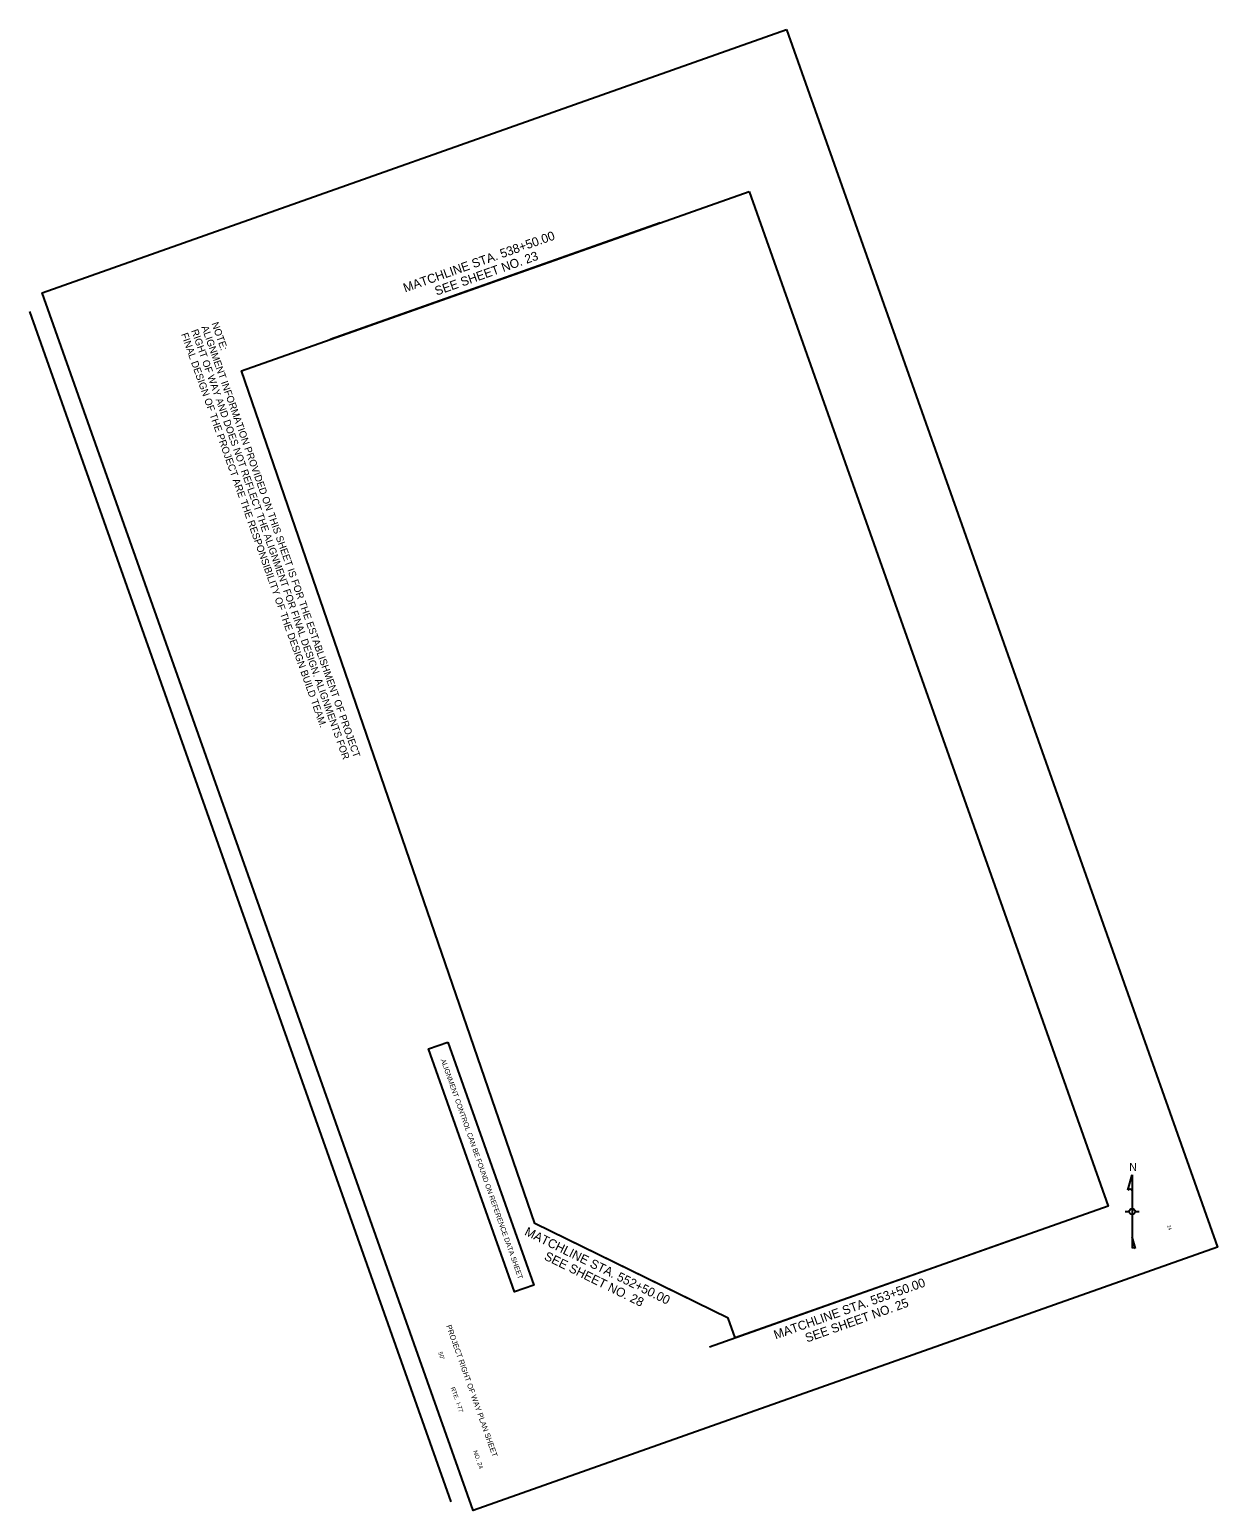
# Model space of a CAD drawing. Extents: x 2004548 to 2006202, y 1137485 to 1139549.
import ezdxf

# ---------------------------------------------------------------- set-up
doc = ezdxf.new("R2010")
doc.units = 0
for name, color, linetype in [('North Arrow', 7, 'Continuous'), ('RD_SHT_IplotShp', 7, 'Continuous'), ('RD_SHT_MatchLine', 7, 'Continuous'), ('RD_SHT_Misc1', 7, 'Continuous'), ('RD_SHT_ShtClip', 7, 'Continuous'), ('RD_SHT_TX', 7, 'Continuous')]:
    doc.layers.add(name, color=color, linetype=linetype)

msp = doc.modelspace()

# ---------------------------------------------------------------- linework, layer by layer
at = {"layer": 'North Arrow'}
for p, q in [((2006077.7, 1137931.5), (2006083.6, 1137952.5)), ((2006083.6, 1137952.5), (2006083.6, 1137930.4)), ((2006083.6, 1137952.5), (2006083.6, 1137850.3)), ((2006073.9, 1137901.4), (2006079.6, 1137901.4)), ((2006087.6, 1137901.4), (2006093.3, 1137901.4)), ((2006083.6, 1137866.1), (2006083.6, 1137850.3)), ((2006088.1, 1137850.1), (2006083.6, 1137866.1))]:
    msp.add_line(p, q, dxfattribs=at)
msp.add_circle((2006083.6, 1137901.4), 4.02, dxfattribs=at)
for centre, radius, start, end in [((2006080.3, 1137929), 3.59, 22.3707, 136.1387), ((2006085.7, 1137847.8), 3.3, 43.3397, 130.5607)]:
    msp.add_arc(centre, radius, start, end, dxfattribs=at)
at = {"layer": 'RD_SHT_IplotShp'}
msp.add_lwpolyline([(2005602, 1139548.8), (2006202.3, 1137851.9), (2005165.3, 1137485), (2004565, 1139181.9)], close=True, dxfattribs=at)
at = {"layer": 'RD_SHT_MatchLine'}
for p, q in [((2005426.1, 1139279.5), (2004966.5, 1139116.9)), ((2005470.7, 1137777.3), (2005251.5, 1137884.9)), ((2005926.3, 1137865.4), (2005494.7, 1137712.7))]:
    msp.add_line(p, q, dxfattribs=at)
at = {"layer": 'RD_SHT_ShtClip'}
msp.add_lwpolyline([(2005549.8, 1139323.3), (2006050.1, 1137909.2), (2005530.3, 1137725.3), (2005520.6, 1137752.8), (2005251.5, 1137884.9), (2004842.7, 1139073.1)], close=True, dxfattribs=at)
at = {"layer": 'RD_SHT_TX'}
msp.add_line((2004547.6, 1139156.1), (2005134.6, 1137496.8), dxfattribs=at)
msp.add_line((2004547.6, 1139156.1), (2005134.6, 1137496.8), dxfattribs=at)
msp.add_lwpolyline([(2005130.3, 1138137.6), (2005250, 1137799), (2005223.3, 1137789.5), (2005103.5, 1138128.1)], close=True, dxfattribs=at)

# ---------------------------------------------------------------- texts
at = {"layer": 'North Arrow'}
msp.add_text('N', height=11.1, dxfattribs=at).set_placement((2006079.5, 1137958))
at = {"layer": 'RD_SHT_MatchLine'}
for s, rotation, p in [('MATCHLINE STA. 538+50.00', 19.482, (2005070.7, 1139182.4)), ('SEE SHEET NO. 23', 19.482, (2005114.6, 1139178)), ('MATCHLINE STA. 552+50.00', 333.8563, (2005236.1, 1137869.4)), ('SEE SHEET NO. 28', 333.8563, (2005263.4, 1137835.1)), ('MATCHLINE STA. 553+50.00', 19.482, (2005586.9, 1137723.3)), ('SEE SHEET NO. 25', 19.482, (2005630.6, 1137718.9))]:
    msp.add_text(s, height=12.5, rotation=rotation, dxfattribs=at).set_placement(p)
at = {"layer": 'RD_SHT_Misc1'}
for s, p in [('NOTE:', (2004800.8, 1139139.2)), ('FINAL DESIGN OF THE PROJECT ARE THE RESPONSIBILITY OF THE DESIGN BUILD TEAM.', (2004758.4, 1139124.2)), ('RIGHT OF WAY AND DOES NOT REFLECT THE ALIGNMENT FOR FINAL DESIGN. ALIGNMENTS FOR', (2004772.5, 1139129.2)), ('ALIGNMENT INFORMATION PROVIDED ON THIS SHEET IS FOR THE ESTABLISHMENT OF PROJECT', (2004786.7, 1139134.2))]:
    msp.add_text(s, height=10, rotation=289.482, dxfattribs=at).set_placement(p)
at = {"layer": 'RD_SHT_TX'}
for s, height, p in [('ALIGNMENT CONTROL CAN BE FOUND ON REFERENCE DATA SHEET', 7, (2005120.2, 1138113)), ('24', 4.5, (2006132.3, 1137881.8)), ('PROJECT RIGHT OF WAY PLAN SHEET', 7.5, (2005127.8, 1137742.1)), ("50'", 6, (2005116.7, 1137704.9)), ('RTE.', 6, (2005134, 1137655.8)), ('I-77', 6, (2005141.6, 1137634.3)), ('NO.', 6, (2005165.3, 1137567.4)), ('24', 6, (2005171.1, 1137551))]:
    msp.add_text(s, height=height, rotation=289.482, dxfattribs=at).set_placement(p)

doc.saveas('drawing.dxf')
